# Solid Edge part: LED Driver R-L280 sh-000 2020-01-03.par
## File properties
Author: radoslaw.kuczynski
Template: iso metric part.par
Last saved by: radoslaw.kuczynski
Revision: 1
Application: Solid Edge
Gęstość: 0,000 kg/m^3
Dokładność: 0,990
Username: radoslaw.kuczynski
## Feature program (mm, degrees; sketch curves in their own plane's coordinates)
body "unnamed Body 1"
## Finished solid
Body 1: solid body, 1029 faces, 2746 edges, 1672 vertices, 3 separate solids.
  Faces by surface: plane 656, cylinder 332, spline 32, cone 9
  Edges by curve: line 1883, circle 675, curve on surface 96, intersection 54, ellipse 38
Bounding box of the edges (mm; curved faces can reach further): 280.000 x 19.978 x 30.000, from (-140, 0, -15) to (140, 19.9777, 15).
Cylindrical faces by radius (mm): R0.002 x4, R0.2 x2, R0.3 x22, R0.4 x1, R0.45 x10, R0.5 x91, R0.5002 x3, R0.502 x4, R0.55 x39, R0.65 x4, R0.7 x4, R0.75 x4, R0.85 x4, R0.8999 x1, R0.9 x10, R0.9001 x1, R1 x31, R1.125 x6, R1.5 x25, R2 x22, R2.1 x20, R3 x6, R3.0987 x1, R3.125 x2, R4.226 x1, R4.5 x1, R5 x8, R6.5 x1, R8 x4
Conical faces (half-angle, radius in mm at the cone's reference point): 45 deg R0.85 x9
Planar faces by outward normal: +x 101, +y 82, +z 78, -x 100, -y 93, -z 84, oblique 118
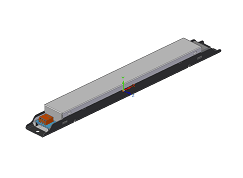
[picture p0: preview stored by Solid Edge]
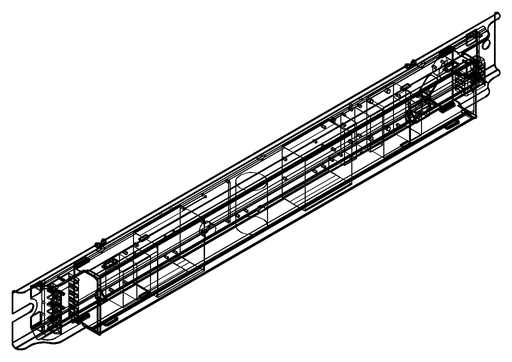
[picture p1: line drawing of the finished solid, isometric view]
